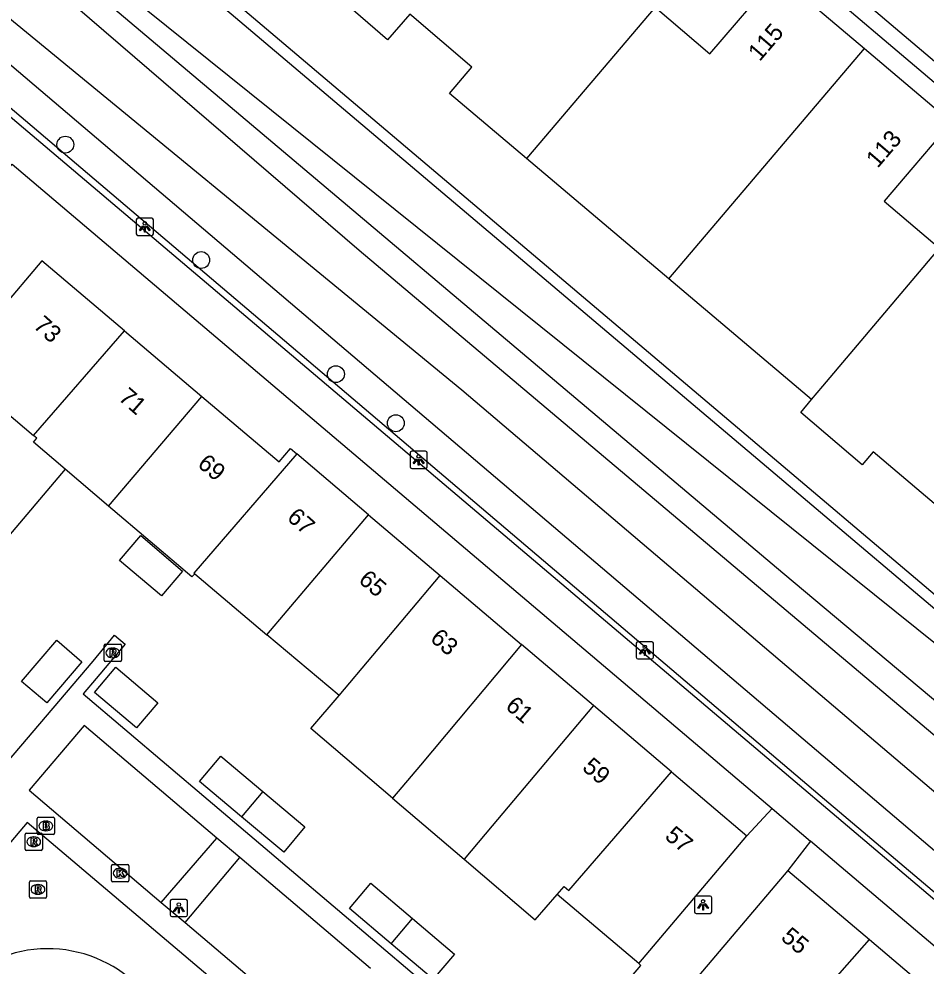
# Model space of a CAD drawing. Extents: x 156414 to 157775, y 382335 to 383765.
# Drawn here: x 156892.2 to 156944.7, y 382528.4 to 382583.3 of the extents above; entities that cross this region are included whole.
import ezdxf

# ---------------------------------------------------------------- set-up
doc = ezdxf.new("R2010")
doc.units = 0
for name, color, linetype in [('IMGEO_Berm_groen', 7, 'Continuous'), ('IMGEO_Boom', 7, 'Continuous'), ('IMGEO_Brandkraan', 7, 'Continuous'), ('IMGEO_Groenvoorziening', 7, 'Continuous'), ('IMGEO_Haag', 7, 'Continuous'), ('IMGEO_Kolk', 7, 'Continuous'), ('IMGEO_Lichtpunt', 7, 'Continuous'), ('IMGEO_Pand', 7, 'Continuous'), ('IMGEO_Pand_nummerreeks', 7, 'Continuous'), ('IMGEO_Rijbaan_lokaal_open', 7, 'Continuous'), ('IMGEO_Rioolput', 7, 'Continuous'), ('IMGEO_Voetpad_open', 7, 'Continuous'), ('IMGEO_Waterloop', 7, 'Continuous')]:
    doc.layers.add(name, color=color, linetype=linetype)

msp = doc.modelspace()

# ---------------------------------------------------------------- linework, layer by layer
at = {"layer": 'IMGEO_Berm_groen'}
msp.add_lwpolyline([(156989.121, 382497.781), (156885.563, 382585.876), (156913.451, 382619.915), (156947.927, 382660.436), (156969.261, 382683.807), (156976.375, 382691.256)], dxfattribs=at)
at = {"layer": 'IMGEO_Boom'}
for centre in [(156894.881, 382576.03), (156902.751, 382569.346), (156910.553, 382562.733), (156914.025, 382559.891)]:
    msp.add_circle(centre, 0.489, dxfattribs=at)
at = {"layer": 'IMGEO_Brandkraan'}
for p, q in [((156893.325, 382537.064), (156894.177, 382537.064)), ((156893.25, 382536.138), (156893.25, 382536.99)), ((156893.738, 382536.844), (156893.763, 382536.844)), ((156894.251, 382536.99), (156894.251, 382536.138)), ((156894.177, 382536.064), (156893.325, 382536.064)), ((156893.761, 382536.284), (156893.736, 382536.284))]:
    msp.add_line(p, q, dxfattribs=at)
for points in [[(156893.325, 382537.064), (156894.177, 382537.064)], [(156893.25, 382536.138), (156893.25, 382536.99)], [(156893.598, 382536.764), (156893.598, 382536.364), (156893.811, 382536.364)], [(156893.829, 382536.764), (156893.598, 382536.764)], [(156893.777, 382536.683), (156893.723, 382536.683), (156893.723, 382536.607)], [(156893.723, 382536.607), (156893.776, 382536.607)], [(156893.785, 382536.531), (156893.723, 382536.531), (156893.723, 382536.45)], [(156893.723, 382536.45), (156893.785, 382536.45)], [(156894.251, 382536.99), (156894.251, 382536.138)], [(156894.177, 382536.064), (156893.325, 382536.064)]]:
    msp.add_lwpolyline(points, dxfattribs=at)
for centre, radius, start, end in [((156893.327, 382536.988), 0.0765, 91.552, 178.448), ((156893.327, 382536.988), 0.0765, 91.552, 178.448), ((156894.175, 382536.988), 0.0765, 1.552, 88.448), ((156894.175, 382536.988), 0.0765, 1.552, 88.448), ((156893.778, 382536.645), 0.0379, 267.8285, 90.9355), ((156893.786, 382536.49), 0.0404, 269.8759, 90.5077), ((156893.833, 382536.619), 0.145, 59.4692, 91.5367), ((156893.858, 382536.666), 0.0922, 285.5137, 58.1501), ((156893.863, 382536.474), 0.105, 301.3115, 78.989), ((156893.327, 382536.14), 0.0765, 181.552, 268.448), ((156893.327, 382536.14), 0.0765, 181.552, 268.448), ((156893.817, 382536.615), 0.251, 268.6676, 293.5347), ((156894.175, 382536.14), 0.0765, 271.552, 358.448), ((156894.175, 382536.14), 0.0765, 271.552, 358.448)]:
    msp.add_arc(centre, radius, start, end, dxfattribs=at)
for centre, major_axis, ratio, start_param, end_param in [((156893.737, 382536.564), (-0.387, 0.002), 0.722429, 4.712389, 7.853982), ((156893.762, 382536.564), (-0.39, 0.002), 0.717154, 1.570796, 4.712389)]:
    msp.add_ellipse(centre, major_axis=major_axis, ratio=ratio, start_param=start_param, end_param=end_param, dxfattribs=at)
at = {"layer": 'IMGEO_Groenvoorziening'}
for points in [[(156980.161, 382688.027), (156972.98, 382679.885), (156951.724, 382654.157), (156930.591, 382629.503), (156894.284, 382586.815), (156936.438, 382551.218), (156974.72, 382519.113), (156990.891, 382505.312), (156993.571, 382503.037)], [(156980.161, 382688.027), (156981.799, 382686.639), (156940.772, 382637.701), (156895.927, 382586.799), (156991.196, 382510.245), (156996.315, 382506.277)]]:
    msp.add_lwpolyline(points, dxfattribs=at)
at = {"layer": 'IMGEO_Haag'}
for points in [[(156986.214, 382682.315), (156986.444, 382682.612), (156986.719, 382682.899), (156984.174, 382685.107), (156900.751, 382586.801), (156978.115, 382521.345), (156996.382, 382542.842), (156996.633, 382543.163)], [(156995.995, 382543.705), (156980.608, 382525.348), (156977.949, 382522.266), (156901.626, 382586.899), (156942.915, 382635.543), (156984.143, 382684.067), (156986.214, 382682.315)], [(156983.94, 382496.877), (156985.472, 382498.688), (156938.603, 382538.304), (156891.556, 382578.272), (156891.296, 382577.994)]]:
    msp.add_lwpolyline(points, dxfattribs=at)
at = {"layer": 'IMGEO_Kolk'}
for p, q in [((156897.556, 382533.402), (156897.556, 382534.254)), ((156897.631, 382534.328), (156898.483, 382534.328)), ((156898.557, 382534.254), (156898.557, 382533.402)), ((156898.044, 382534.108), (156898.069, 382534.108)), ((156898.483, 382533.328), (156897.631, 382533.328)), ((156898.067, 382533.548), (156898.042, 382533.548))]:
    msp.add_line(p, q, dxfattribs=at)
for points in [[(156897.556, 382533.402), (156897.556, 382534.254)], [(156897.631, 382534.328), (156898.483, 382534.328)], [(156898.557, 382534.254), (156898.557, 382533.402)], [(156897.877, 382534.028), (156898, 382534.028), (156898, 382533.877), (156898.13, 382534.028), (156898.294, 382534.028), (156898.148, 382533.877), (156898.301, 382533.628), (156898.149, 382533.628), (156898.064, 382533.792), (156898, 382533.725), (156898, 382533.628), (156897.877, 382533.628), (156897.877, 382534.028)], [(156898.483, 382533.328), (156897.631, 382533.328)]]:
    msp.add_lwpolyline(points, dxfattribs=at)
for centre, start, end in [((156897.633, 382534.252), 91.552, 178.448), ((156897.633, 382534.252), 91.552, 178.448), ((156898.481, 382534.252), 1.552, 88.448), ((156898.481, 382534.252), 1.552, 88.448), ((156897.633, 382533.404), 181.552, 268.448), ((156897.633, 382533.404), 181.552, 268.448), ((156898.481, 382533.404), 271.552, 358.448), ((156898.481, 382533.404), 271.552, 358.448)]:
    msp.add_arc(centre, 0.0765, start, end, dxfattribs=at)
for centre, major_axis, ratio, start_param, end_param in [((156898.043, 382533.828), (-0.387, 0.002), 0.722429, 4.712389, 7.853982), ((156898.068, 382533.828), (-0.39, 0.002), 0.717154, 1.570796, 4.712389)]:
    msp.add_ellipse(centre, major_axis=major_axis, ratio=ratio, start_param=start_param, end_param=end_param, dxfattribs=at)
at = {"layer": 'IMGEO_Lichtpunt'}
for p, q in [((156898.987, 382571.672), (156898.987, 382570.865)), ((156898.987, 382571.672), (156898.987, 382570.865)), ((156899.889, 382571.767), (156899.081, 382571.767)), ((156899.889, 382571.767), (156899.081, 382571.767)), ((156899.983, 382570.865), (156899.983, 382571.672)), ((156899.983, 382570.865), (156899.983, 382571.672)), ((156899.081, 382570.771), (156899.889, 382570.771)), ((156899.081, 382570.771), (156899.889, 382570.771)), ((156914.848, 382558.175), (156914.848, 382557.368)), ((156914.848, 382558.175), (156914.848, 382557.368)), ((156915.75, 382558.27), (156914.942, 382558.27)), ((156915.75, 382558.27), (156914.942, 382558.27)), ((156915.844, 382557.368), (156915.844, 382558.175)), ((156915.844, 382557.368), (156915.844, 382558.175)), ((156914.942, 382557.274), (156915.75, 382557.274)), ((156914.942, 382557.274), (156915.75, 382557.274)), ((156927.95, 382547.144), (156927.95, 382546.337)), ((156927.95, 382547.144), (156927.95, 382546.337)), ((156928.852, 382547.239), (156928.044, 382547.239)), ((156928.852, 382547.239), (156928.044, 382547.239)), ((156928.946, 382546.337), (156928.946, 382547.144)), ((156928.946, 382546.337), (156928.946, 382547.144)), ((156928.044, 382546.243), (156928.852, 382546.243)), ((156928.044, 382546.243), (156928.852, 382546.243)), ((156900.958, 382532.217), (156900.958, 382531.41)), ((156900.958, 382532.217), (156900.958, 382531.41)), ((156901.86, 382532.312), (156901.052, 382532.312)), ((156901.86, 382532.312), (156901.052, 382532.312)), ((156901.954, 382531.41), (156901.954, 382532.217)), ((156901.954, 382531.41), (156901.954, 382532.217)), ((156931.322, 382532.401), (156931.322, 382531.594)), ((156931.322, 382532.401), (156931.322, 382531.594)), ((156932.224, 382532.496), (156931.416, 382532.496)), ((156932.224, 382532.496), (156931.416, 382532.496)), ((156932.318, 382531.594), (156932.318, 382532.401)), ((156932.318, 382531.594), (156932.318, 382532.401)), ((156901.052, 382531.316), (156901.86, 382531.316)), ((156901.052, 382531.316), (156901.86, 382531.316)), ((156931.416, 382531.5), (156932.224, 382531.5)), ((156931.416, 382531.5), (156932.224, 382531.5))]:
    msp.add_line(p, q, dxfattribs=at)
for points in [[(156899.361, 382571.336), (156899.4, 382571.308), (156899.212, 382571.046), (156899.174, 382571.073), (156899.361, 382571.336)], [(156899.463, 382571.288), (156899.51, 382571.288), (156899.51, 382570.966), (156899.463, 382570.966), (156899.463, 382571.288)], [(156899.573, 382571.308), (156899.611, 382571.335), (156899.798, 382571.073), (156899.759, 382571.045), (156899.573, 382571.308)], [(156915.222, 382557.839), (156915.261, 382557.811), (156915.073, 382557.549), (156915.035, 382557.576), (156915.222, 382557.839)], [(156915.324, 382557.791), (156915.371, 382557.791), (156915.371, 382557.469), (156915.324, 382557.469), (156915.324, 382557.791)], [(156915.434, 382557.811), (156915.472, 382557.838), (156915.659, 382557.576), (156915.62, 382557.548), (156915.434, 382557.811)], [(156928.324, 382546.808), (156928.363, 382546.78), (156928.175, 382546.518), (156928.137, 382546.545), (156928.324, 382546.808)], [(156928.426, 382546.76), (156928.473, 382546.76), (156928.473, 382546.438), (156928.426, 382546.438), (156928.426, 382546.76)], [(156928.536, 382546.78), (156928.574, 382546.807), (156928.761, 382546.545), (156928.722, 382546.517), (156928.536, 382546.78)], [(156931.696, 382532.065), (156931.735, 382532.037), (156931.547, 382531.775), (156931.509, 382531.802), (156931.696, 382532.065)], [(156931.908, 382532.037), (156931.946, 382532.064), (156932.133, 382531.802), (156932.094, 382531.774), (156931.908, 382532.037)], [(156901.332, 382531.881), (156901.371, 382531.853), (156901.183, 382531.591), (156901.145, 382531.618), (156901.332, 382531.881)], [(156901.434, 382531.833), (156901.481, 382531.833), (156901.481, 382531.511), (156901.434, 382531.511), (156901.434, 382531.833)], [(156901.544, 382531.853), (156901.582, 382531.88), (156901.769, 382531.618), (156901.73, 382531.59), (156901.544, 382531.853)], [(156931.798, 382532.017), (156931.845, 382532.017), (156931.845, 382531.695), (156931.798, 382531.695), (156931.798, 382532.017)]]:
    msp.add_lwpolyline(points, dxfattribs=at)
for centre in [(156899.486, 382571.47), (156915.347, 382557.973), (156928.449, 382546.942), (156901.457, 382532.015), (156931.821, 382532.199)]:
    msp.add_circle(centre, 0.0994, dxfattribs=at)
for centre, start, end in [((156899.081, 382571.672), 90, 180), ((156899.081, 382571.672), 90, 180), ((156899.889, 382571.672), 0, 90), ((156899.889, 382571.672), 0, 90), ((156899.081, 382570.865), 180, 270), ((156899.081, 382570.865), 180, 270), ((156899.889, 382570.865), 270, 0), ((156899.889, 382570.865), 270, 360), ((156914.942, 382558.175), 90, 180), ((156914.942, 382558.175), 90, 180), ((156915.75, 382558.175), 0, 90), ((156915.75, 382558.175), 0, 90), ((156914.942, 382557.368), 180, 270), ((156914.942, 382557.368), 180, 270), ((156915.75, 382557.368), 270, 0), ((156915.75, 382557.368), 270, 360), ((156928.044, 382547.144), 90, 180), ((156928.044, 382547.144), 90, 180), ((156928.852, 382547.144), 0, 90), ((156928.852, 382547.144), 0, 90), ((156928.044, 382546.337), 180, 270), ((156928.044, 382546.337), 180, 270), ((156928.852, 382546.337), 270, 0), ((156928.852, 382546.337), 270, 360), ((156901.052, 382532.217), 90, 180), ((156901.052, 382532.217), 90, 180), ((156901.86, 382532.217), 0, 90), ((156901.86, 382532.217), 0, 90), ((156931.416, 382532.401), 90, 180), ((156931.416, 382532.401), 90, 180), ((156932.224, 382532.401), 0, 90), ((156932.224, 382532.401), 0, 90), ((156931.416, 382531.594), 180, 270), ((156931.416, 382531.594), 180, 270), ((156932.224, 382531.594), 270, 0), ((156932.224, 382531.594), 270, 360), ((156901.052, 382531.41), 180, 270), ((156901.052, 382531.41), 180, 270), ((156901.86, 382531.41), 270, 0), ((156901.86, 382531.41), 270, 360)]:
    msp.add_arc(centre, 0.0946, start, end, dxfattribs=at)
at = {"layer": 'IMGEO_Pand'}
for points in [[(156914.956, 382583.498), (156914.841, 382583.596), (156913.54, 382582.111), (156910.127, 382585.077), (156912.851, 382588.274), (156910.012, 382590.693), (156922.478, 382605.328), (156924.467, 382603.646), (156928.89, 382599.864), (156925.007, 382595.303)], [(156929.041, 382583.989), (156932.219, 382581.282), (156936.129, 382585.872), (156941.165, 382581.599)], [(156929.041, 382583.989), (156921.586, 382575.237)], [(156921.586, 382575.237), (156917.14, 382578.999), (156918.431, 382580.526), (156914.956, 382583.498)], [(156929.841, 382568.253), (156941.165, 382581.599)], [(156941.165, 382581.599), (156946.201, 382577.326), (156943.973, 382574.706), (156942.307, 382572.748), (156945.523, 382570.026)], [(156929.841, 382568.253), (156921.586, 382575.237)], [(156938.104, 382561.262), (156938.762, 382562.039), (156945.523, 382570.026)], [(156898.301, 382565.253), (156893.528, 382569.305), (156891.093, 382566.436), (156889.231, 382568.016), (156887.752, 382566.274), (156889.614, 382564.694), (156888.435, 382563.304)], [(156938.104, 382561.262), (156929.841, 382568.253)], [(156893.039, 382559.173), (156898.301, 382565.253)], [(156898.301, 382565.253), (156902.783, 382561.45)], [(156888.435, 382563.304), (156888.325, 382563.174), (156893.039, 382559.173)], [(156897.389, 382555.095), (156902.783, 382561.45)], [(156902.783, 382561.45), (156907.264, 382557.647), (156907.923, 382558.424), (156908.29, 382558.113)], [(156947.289, 382555.394), (156947.03, 382555.088), (156946.346, 382554.281), (156941.671, 382558.233), (156941.039, 382557.486), (156937.477, 382560.522), (156938.104, 382561.262)], [(156894.876, 382557.231), (156893.03, 382558.798), (156893.222, 382559.018), (156893.039, 382559.173)], [(156908.29, 382558.113), (156902.32, 382551.216), (156902.38, 382551.165)], [(156912.438, 382554.596), (156908.29, 382558.113)], [(156894.876, 382557.231), (156891.168, 382552.855), (156889.271, 382554.502)], [(156897.389, 382555.095), (156894.876, 382557.231)], [(156902.38, 382551.165), (156902.218, 382550.988), (156897.389, 382555.095)], [(156906.559, 382547.64), (156912.438, 382554.596)], [(156912.438, 382554.596), (156916.585, 382551.078)], [(156900.452, 382549.892), (156898.026, 382551.935), (156899.246, 382553.384), (156901.663, 382551.329), (156900.452, 382549.892)], [(156902.38, 382551.165), (156906.559, 382547.64)], [(156910.737, 382544.115), (156916.585, 382551.078)], [(156916.585, 382551.078), (156921.309, 382547.072)], [(156910.737, 382544.115), (156906.559, 382547.64)], [(156893.805, 382543.692), (156892.348, 382544.938), (156894.382, 382547.317), (156895.839, 382546.071), (156893.805, 382543.692)], [(156921.309, 382547.072), (156915.447, 382540.092), (156913.831, 382538.175)], [(156925.465, 382543.547), (156921.309, 382547.072)], [(156898.997, 382542.241), (156896.576, 382544.29), (156897.815, 382545.754), (156900.236, 382543.705), (156898.997, 382542.241)], [(156913.831, 382538.175), (156909.108, 382542.206), (156910.737, 382544.115)], [(156925.465, 382543.547), (156919.611, 382536.577), (156917.979, 382534.634)], [(156929.993, 382539.707), (156925.465, 382543.547)], [(156905.094, 382537.094), (156902.661, 382539.148), (156903.896, 382540.612), (156906.33, 382538.558)], [(156923.378, 382532.595), (156923.767, 382533.052), (156924.035, 382532.824), (156929.993, 382539.707)], [(156929.993, 382539.707), (156934.364, 382536)], [(156906.33, 382538.558), (156908.763, 382536.505), (156907.528, 382535.041), (156905.094, 382537.094)], [(156906.33, 382538.558), (156905.094, 382537.094)], [(156913.831, 382538.175), (156917.979, 382534.634)], [(156928.09, 382528.588), (156934.364, 382536)], [(156917.979, 382534.634), (156922.1, 382531.118), (156923.378, 382532.595)], [(156936.736, 382533.985), (156930.077, 382526.127)], [(156936.736, 382533.985), (156941.459, 382529.981)], [(156913.76, 382529.736), (156911.335, 382531.785), (156912.567, 382533.244), (156914.992, 382531.195)], [(156928.09, 382528.588), (156923.378, 382532.595)], [(156914.992, 382531.195), (156917.418, 382529.146), (156916.186, 382527.687), (156913.76, 382529.736)], [(156913.76, 382529.736), (156914.992, 382531.195)], [(156935.57, 382523.04), (156935.444, 382523.146), (156941.459, 382529.981)], [(156941.459, 382529.981), (156945.561, 382526.504)]]:
    msp.add_lwpolyline(points, dxfattribs=at)
at = {"layer": 'IMGEO_Rijbaan_lokaal_open'}
for points in [[(156985.195, 382552.172), (156984.601, 382552.665), (156982.077, 382549.644), (156927.619, 382595.781), (156937.011, 382606.884), (156991.519, 382560.783), (156988.981, 382557.799), (156989.555, 382557.259)], [(156942.158, 382490.336), (156944.379, 382492.961), (156905.035, 382526.295), (156892.664, 382536.77), (156890.546, 382534.28)]]:
    msp.add_lwpolyline(points, dxfattribs=at)
msp.add_arc((156893.866, 382522.029), 7.423, 50.8408, 141.5317, dxfattribs=at)
at = {"layer": 'IMGEO_Rioolput'}
for p, q in [((156897.13, 382546.165), (156897.13, 382547.017)), ((156897.205, 382547.091), (156898.057, 382547.091)), ((156898.131, 382547.017), (156898.131, 382546.165)), ((156897.618, 382546.871), (156897.643, 382546.871)), ((156898.057, 382546.091), (156897.205, 382546.091)), ((156897.641, 382546.311), (156897.616, 382546.311)), ((156892.55, 382535.222), (156892.55, 382536.074)), ((156892.625, 382536.148), (156893.477, 382536.148)), ((156893.038, 382535.928), (156893.063, 382535.928)), ((156893.551, 382536.074), (156893.551, 382535.222)), ((156893.061, 382535.368), (156893.036, 382535.368)), ((156893.477, 382535.148), (156892.625, 382535.148)), ((156892.797, 382532.461), (156892.797, 382533.313)), ((156892.872, 382533.387), (156893.724, 382533.387)), ((156893.285, 382533.167), (156893.31, 382533.167)), ((156893.798, 382533.313), (156893.798, 382532.461)), ((156893.308, 382532.607), (156893.283, 382532.607)), ((156893.724, 382532.387), (156892.872, 382532.387))]:
    msp.add_line(p, q, dxfattribs=at)
for points in [[(156897.13, 382546.165), (156897.13, 382547.017)], [(156897.205, 382547.091), (156898.057, 382547.091)], [(156898.131, 382547.017), (156898.131, 382546.165)], [(156897.719, 382546.789), (156897.467, 382546.791), (156897.467, 382546.391)], [(156897.467, 382546.391), (156897.591, 382546.391), (156897.591, 382546.553), (156897.602, 382546.553)], [(156897.645, 382546.71), (156897.591, 382546.71), (156897.591, 382546.629)], [(156897.591, 382546.629), (156897.643, 382546.629)], [(156897.649, 382546.524), (156897.72, 382546.391), (156897.86, 382546.391), (156897.795, 382546.517)], [(156898.057, 382546.091), (156897.205, 382546.091)], [(156892.55, 382535.222), (156892.55, 382536.074)], [(156892.625, 382536.148), (156893.477, 382536.148)], [(156893.551, 382536.074), (156893.551, 382535.222)], [(156893.139, 382535.846), (156892.887, 382535.848), (156892.887, 382535.448)], [(156892.887, 382535.448), (156893.011, 382535.448), (156893.011, 382535.61), (156893.022, 382535.61)], [(156893.065, 382535.767), (156893.011, 382535.767), (156893.011, 382535.686)], [(156893.011, 382535.686), (156893.063, 382535.686)], [(156893.069, 382535.581), (156893.14, 382535.448), (156893.28, 382535.448), (156893.215, 382535.574)], [(156893.477, 382535.148), (156892.625, 382535.148)], [(156892.797, 382532.461), (156892.797, 382533.313)], [(156892.872, 382533.387), (156893.724, 382533.387)], [(156893.798, 382533.313), (156893.798, 382532.461)], [(156893.386, 382533.085), (156893.134, 382533.087), (156893.134, 382532.687)], [(156893.134, 382532.687), (156893.258, 382532.687), (156893.258, 382532.849), (156893.269, 382532.849)], [(156893.312, 382533.006), (156893.258, 382533.006), (156893.258, 382532.925)], [(156893.258, 382532.925), (156893.31, 382532.925)], [(156893.316, 382532.82), (156893.387, 382532.687), (156893.527, 382532.687), (156893.462, 382532.813)], [(156893.724, 382532.387), (156892.872, 382532.387)]]:
    msp.add_lwpolyline(points, dxfattribs=at)
for centre, radius, start, end in [((156897.207, 382547.015), 0.0765, 91.552, 178.448), ((156897.207, 382547.015), 0.0765, 91.552, 178.448), ((156898.055, 382547.015), 0.0765, 1.552, 88.448), ((156898.055, 382547.015), 0.0765, 1.552, 88.448), ((156897.601, 382546.5), 0.0533, 26.0293, 88.6989), ((156897.627, 382546.818), 0.19, 274.7715, 282.9687), ((156897.651, 382546.614), 0.0964, 77.0061, 93.1865), ((156897.665, 382546.671), 0.0378, 276.6634, 79.6772), ((156897.718, 382546.679), 0.109, 350.3612, 89.416), ((156897.716, 382546.679), 0.112, 277.5842, 350.9817), ((156897.7, 382546.464), 0.108, 29.5134, 73.7905), ((156897.207, 382546.167), 0.0765, 181.552, 268.448), ((156897.207, 382546.167), 0.0765, 181.552, 268.448), ((156898.055, 382546.167), 0.0765, 271.552, 358.448), ((156898.055, 382546.167), 0.0765, 271.552, 358.448), ((156892.627, 382536.072), 0.0765, 91.552, 178.448), ((156892.627, 382536.072), 0.0765, 91.552, 178.448), ((156893.475, 382536.072), 0.0765, 1.552, 88.448), ((156893.475, 382536.072), 0.0765, 1.552, 88.448), ((156893.021, 382535.557), 0.0533, 26.0293, 88.6989), ((156893.047, 382535.875), 0.19, 274.7715, 282.9687), ((156893.071, 382535.671), 0.0964, 77.0061, 93.1865), ((156893.085, 382535.728), 0.0378, 276.6634, 79.6772), ((156893.138, 382535.736), 0.109, 350.3612, 89.416), ((156893.136, 382535.736), 0.112, 277.5842, 350.9817), ((156893.12, 382535.521), 0.108, 29.5134, 73.7905), ((156892.627, 382535.224), 0.0765, 181.552, 268.448), ((156892.627, 382535.224), 0.0765, 181.552, 268.448), ((156893.475, 382535.224), 0.0765, 271.552, 358.448), ((156893.475, 382535.224), 0.0765, 271.552, 358.448), ((156892.874, 382533.311), 0.0765, 91.552, 178.448), ((156892.874, 382533.311), 0.0765, 91.552, 178.448), ((156893.722, 382533.311), 0.0765, 1.552, 88.448), ((156893.722, 382533.311), 0.0765, 1.552, 88.448), ((156893.268, 382532.796), 0.0533, 26.0293, 88.6989), ((156893.294, 382533.114), 0.19, 274.7715, 282.9687), ((156893.318, 382532.91), 0.0964, 77.0061, 93.1865), ((156893.332, 382532.967), 0.0378, 276.6634, 79.6772), ((156893.385, 382532.975), 0.109, 350.3612, 89.416), ((156893.383, 382532.975), 0.112, 277.5842, 350.9817), ((156893.367, 382532.76), 0.108, 29.5134, 73.7905), ((156892.874, 382532.463), 0.0765, 181.552, 268.448), ((156892.874, 382532.463), 0.0765, 181.552, 268.448), ((156893.722, 382532.463), 0.0765, 271.552, 358.448), ((156893.722, 382532.463), 0.0765, 271.552, 358.448)]:
    msp.add_arc(centre, radius, start, end, dxfattribs=at)
for centre, major_axis, ratio, start_param, end_param in [((156897.617, 382546.591), (-0.387, 0.002), 0.722429, 4.712389, 7.853982), ((156897.642, 382546.591), (-0.39, 0.002), 0.717154, 1.570796, 4.712389), ((156893.037, 382535.648), (-0.387, 0.002), 0.722429, 4.712389, 7.853982), ((156893.062, 382535.648), (-0.39, 0.002), 0.717154, 1.570796, 4.712389), ((156893.284, 382532.887), (-0.387, 0.002), 0.722429, 4.712389, 7.853982), ((156893.309, 382532.887), (-0.39, 0.002), 0.717154, 1.570796, 4.712389)]:
    msp.add_ellipse(centre, major_axis=major_axis, ratio=ratio, start_param=start_param, end_param=end_param, dxfattribs=at)
at = {"layer": 'IMGEO_Voetpad_open'}
for points in [[(156985.096, 382551.062), (156984.751, 382551.362), (156982.188, 382548.489), (156956.652, 382569.938), (156926.325, 382595.645), (156936.95, 382608.202), (156992.775, 382560.898), (156990.241, 382557.869), (156990.622, 382557.547)], [(156891.296, 382577.994), (156891.573, 382577.76), (156984.878, 382498.701), (156983.583, 382497.172), (156983.94, 382496.877)], [(156872.346, 382551.963), (156891.803, 382574.898), (156935.828, 382537.574)], [(156872.346, 382551.963), (156882.867, 382543.058), (156882.788, 382542.965), (156889.195, 382537.565), (156896.503, 382546.111), (156897.724, 382547.619), (156898.343, 382547.085), (156896.673, 382545.097), (156895.919, 382544.208), (156922.464, 382521.705), (156928.221, 382528.476), (156928.09, 382528.588)], [(156903.657, 382535.864), (156895.977, 382542.378), (156892.782, 382538.633), (156900.442, 382532.138)], [(156934.364, 382536), (156935.828, 382537.574)], [(156935.828, 382537.574), (156938.049, 382535.675)], [(156900.442, 382532.138), (156903.657, 382535.864)], [(156904.984, 382534.738), (156903.657, 382535.864)], [(156938.049, 382535.675), (156936.736, 382533.985)], [(156962.546, 382475.543), (156981.989, 382498.437), (156938.049, 382535.675)], [(156901.814, 382530.975), (156904.984, 382534.738)], [(156912.564, 382528.308), (156904.984, 382534.738)], [(156900.442, 382532.138), (156901.814, 382530.975)], [(156901.814, 382530.975), (156909.391, 382524.55)]]:
    msp.add_lwpolyline(points, dxfattribs=at)
at = {"layer": 'IMGEO_Waterloop'}
msp.add_lwpolyline([(156976.651, 382689.094), (156938.817, 382644.211), (156919.284, 382621.196), (156897.458, 382595.718), (156888.498, 382585.952), (156917.84, 382561.833), (156974.953, 382513.255), (156988.286, 382501.918), (156990.282, 382503.616), (156950.791, 382537.119), (156911.895, 382569.901), (156892.83, 382586.334), (156913.254, 382611.005), (156944.082, 382646.376), (156967.14, 382674.699), (156978.605, 382687.65), (156976.651, 382689.094)], dxfattribs=at)

# ---------------------------------------------------------------- texts
at = {"layer": 'IMGEO_Pand_nummerreeks'}
for s, rotation, p in [('115', 49.3775, (156935.095, 382580.81)), ('113', 49.4233, (156941.93, 382574.627)), ('73', 318.3116, (156892.977, 382565.465)), ('71', 319.147, (156897.899, 382561.283)), ('69', 320.4116, (156902.479, 382557.428)), ('67', 318.2552, (156907.664, 382554.345)), ('65', 319.5049, (156911.806, 382550.723)), ('63', 319.2954, (156915.954, 382547.335)), ('61', 319.1768, (156920.315, 382543.413)), ('59', 319.4862, (156924.763, 382539.86)), ('57', 320.5632, (156929.547, 382535.874)), ('55', 320.3803, (156936.271, 382530.015))]:
    msp.add_text(s, height=1, rotation=rotation, dxfattribs=at).set_placement(p)

doc.saveas('drawing.dxf')
